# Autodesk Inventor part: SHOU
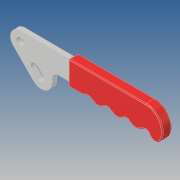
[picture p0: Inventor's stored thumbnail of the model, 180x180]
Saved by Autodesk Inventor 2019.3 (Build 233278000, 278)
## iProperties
Created: 2017-08
Part Number: SHOU
Material: Ogólny
Document SubType Name: Modeling
Designer: Admin
Density: 1 g/cm^3
Appearance: Domyślna
Author: Admin
Revision Number: ÈÎºÎ
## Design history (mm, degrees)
feature "ÊäÈë1"
node "Bryła1"
